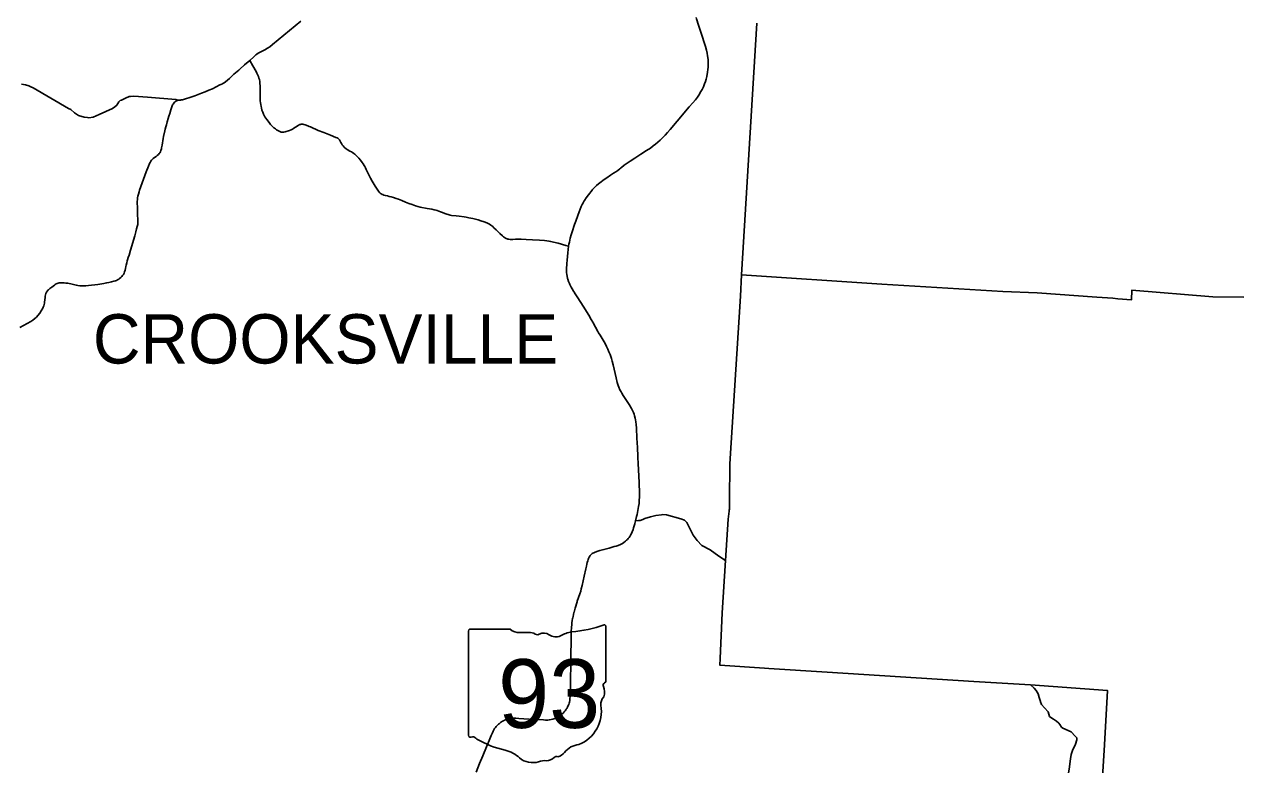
# Model space of a CAD drawing. Extents: x 1761803 to 2441803, y 509895 to 949895.
# Drawn here: x 2058370 to 2107842, y 720477 to 750488 of the extents above; entities that cross this region are included whole.
import ezdxf

# ---------------------------------------------------------------- set-up
doc = ezdxf.new("R2010")
doc.units = 0
for name, color, linetype in [('GM_X_County', 7, 'Continuous'), ('GM_X_County_Road', 7, 'Continuous'), ('GM_X_Minor_Lake', 7, 'Continuous'), ('GM_X_Township_Road', 7, 'Continuous')]:
    doc.layers.add(name, color=color, linetype=linetype)

msp = doc.modelspace()

# ---------------------------------------------------------------- linework, layer by layer
at = {"layer": 'GM_X_County'}
for points in [[(2101907, 716726), (2102194, 721282), (2102313, 723484), (2099188, 723707), (2096896, 723844), (2090939, 724221), (2088582, 724377), (2088401, 724389), (2086592, 724508), (2086607, 724783), (2086686, 726634), (2086822, 728750), (2086931, 730426), (2086970, 730749), (2086973, 730788), (2086976, 730834), (2086979, 730892), (2086981, 730973), (2086981, 731041), (2086978, 731135), (2086980, 731181), (2087001, 732668), (2087421, 739471), (2087469, 740337), (2088090, 750532)], [(2107855, 739434), (2106588, 739441), (2103300, 739712), (2103287, 739317), (2102743, 739362), (2102541, 739394), (2101889, 739433), (2099468, 739598), (2098068, 739659), (2093166, 739956), (2087469, 740337)]]:
    msp.add_lwpolyline(points, dxfattribs=at)
at = {"layer": 'GM_X_Minor_Lake'}
for points in [[(2068067, 749429), (2068070, 749430), (2068133, 749461), (2068231, 749519), (2068325, 749583), (2068440, 749673), (2069593, 750613)], [(2085804, 750213), (2085723, 750464), (2085643, 750717), (2085628, 750763)], [(2085491, 747313), (2085602, 747435), (2085685, 747544), (2085736, 747618), (2085823, 747764), (2085870, 747855), (2085920, 747958), (2085967, 748072), (2086005, 748177), (2086034, 748267), (2086062, 748380), (2086094, 748553), (2086106, 748664), (2086114, 748752), (2086117, 748856), (2086119, 748941), (2086111, 749068), (2086094, 749220), (2086073, 749328), (2086046, 749446), (2086005, 749590), (2085819, 750168), (2085804, 750213)], [(2067067, 748635), (2067106, 748670), (2067308, 748851), (2067512, 749028), (2067675, 749176), (2067714, 749209), (2067763, 749250), (2067806, 749284), (2067857, 749318), (2067904, 749347), (2068067, 749429)], [(2067512, 749028), (2067641, 748808), (2067774, 748574), (2067805, 748511), (2067832, 748456), (2067865, 748377), (2067887, 748314), (2067906, 748248), (2067920, 748176), (2067928, 748097), (2067934, 748004), (2067938, 747642), (2067938, 747517), (2067943, 747395), (2067953, 747302), (2067961, 747236), (2067973, 747159), (2067986, 747106), (2068010, 747017), (2068043, 746929), (2068078, 746848), (2068130, 746746), (2068171, 746680), (2068210, 746626), (2068296, 746516), (2068363, 746434), (2068439, 746354), (2068494, 746299), (2068518, 746278), (2068555, 746248), (2068600, 746219), (2068656, 746187), (2068709, 746158), (2068762, 746136), (2068795, 746125), (2068835, 746119), (2068869, 746119), (2068902, 746124), (2068958, 746138), (2069127, 746192), (2069196, 746218), (2069249, 746243), (2069291, 746268), (2069344, 746304), (2069396, 746340), (2069450, 746375), (2069481, 746395), (2069513, 746413), (2069539, 746426), (2069567, 746436), (2069596, 746441), (2069618, 746444), (2069643, 746444), (2069667, 746441), (2069705, 746433), (2069768, 746414), (2069871, 746377), (2069932, 746353), (2069978, 746331), (2070293, 746190), (2070520, 746100), (2070796, 745993), (2071010, 745909), (2071061, 745887), (2071088, 745872), (2071115, 745852), (2071134, 745832), (2071158, 745804), (2071182, 745757), (2071209, 745704), (2071238, 745658), (2071267, 745612), (2071302, 745565), (2071341, 745517), (2071375, 745483), (2071424, 745441), (2071470, 745411), (2071582, 745350), (2071640, 745319), (2071682, 745292), (2071734, 745257), (2071782, 745222), (2071837, 745173), (2071879, 745131), (2071937, 745067), (2072003, 744988), (2072074, 744891), (2072114, 744832), (2072156, 744769), (2072182, 744725), (2072212, 744673), (2072244, 744612), (2072334, 744419), (2072416, 744256), (2072485, 744136), (2072609, 743931), (2072740, 743723), (2072768, 743686), (2072802, 743650), (2072846, 743617), (2072886, 743596), (2072910, 743585), (2072911, 743585), (2072955, 743569), (2073022, 743550), (2073104, 743532), (2073178, 743513), (2073255, 743493), (2073344, 743467), (2073457, 743432), (2073545, 743402), (2073685, 743352), (2073839, 743287), (2073976, 743230), (2074098, 743180), (2074238, 743130), (2074331, 743104), (2074435, 743081), (2074707, 743029), (2074907, 742993), (2074993, 742975), (2075068, 742957), (2075125, 742941), (2075257, 742893), (2075330, 742863), (2075424, 742826), (2075509, 742796), (2075563, 742776), (2075646, 742755), (2075703, 742744), (2075893, 742722), (2076013, 742710), (2076211, 742685), (2076294, 742673), (2076410, 742648), (2076564, 742615), (2076681, 742589), (2076789, 742560), (2076897, 742524), (2077027, 742478), (2077133, 742439), (2077193, 742413), (2077245, 742385), (2077299, 742350), (2077376, 742288), (2077425, 742245), (2077517, 742161), (2077661, 742017), (2077764, 741911), (2077811, 741871), (2077846, 741846), (2077888, 741822), (2077923, 741805), (2077961, 741791), (2077991, 741782), (2078022, 741776), (2078075, 741769), (2078166, 741770), (2078196, 741772)], [(2064269, 746875), (2064314, 747020), (2064314, 747021), (2064343, 747109), (2064369, 747180), (2064386, 747224), (2064404, 747259), (2064428, 747298), (2064458, 747329), (2064488, 747353), (2064520, 747374), (2064548, 747389), (2064578, 747399), (2064624, 747411), (2064663, 747414), (2064701, 747419), (2064736, 747425), (2064781, 747435), (2064861, 747455), (2064947, 747480), (2065048, 747512), (2065199, 747563), (2065283, 747593), (2065559, 747698), (2065710, 747756), (2065859, 747818), (2066000, 747880), (2066297, 748033), (2066377, 748068), (2066423, 748091), (2066475, 748123), (2066528, 748159), (2066612, 748227), (2066691, 748296), (2066875, 748465), (2067067, 748635)], [(2058247, 748065), (2058411, 748043), (2058549, 748003), (2058634, 747961), (2058725, 747917), (2060163, 747078), (2060248, 747032), (2060406, 746900), (2060572, 746799), (2060792, 746725), (2060926, 746709), (2060979, 746703), (2061161, 746729), (2061403, 746829), (2061945, 747085), (2062045, 747147), (2062121, 747217), (2062207, 747351), (2062253, 747399), (2062305, 747423), (2062471, 747497), (2062619, 747559), (2062673, 747571), (2062810, 747577), (2063362, 747543), (2064514, 747440), (2064560, 747429), (2064624, 747411)], [(2082561, 744655), (2082604, 744688), (2082713, 744775), (2082824, 744856), (2082944, 744945), (2083140, 745069), (2083382, 745224), (2083617, 745375), (2083770, 745476), (2083885, 745562), (2083978, 745636), (2084076, 745716), (2084169, 745799), (2084274, 745899), (2084371, 745998), (2084467, 746105), (2084571, 746225), (2084856, 746562), (2085342, 747144), (2085491, 747313)], [(2058182, 738196), (2058634, 738445), (2058666, 738465), (2058719, 738500), (2058800, 738565), (2058855, 738619), (2058911, 738682), (2058990, 738782), (2059055, 738881), (2059116, 738987), (2059131, 739020), (2059132, 739025), (2059153, 739078), (2059170, 739133), (2059181, 739180), (2059190, 739233), (2059197, 739320), (2059211, 739418), (2059219, 739475), (2059229, 739523), (2059243, 739572), (2059254, 739602), (2059265, 739626), (2059277, 739646), (2059294, 739672), (2059305, 739690), (2059325, 739711), (2059347, 739733), (2059371, 739755), (2059404, 739782), (2059480, 739839), (2059590, 739917), (2059623, 739940), (2059660, 739963), (2059699, 739981), (2059739, 739996), (2059784, 740006), (2059822, 740009), (2059878, 740013), (2059930, 740011), (2059983, 740008), (2060049, 740002), (2060128, 739990), (2060306, 739952), (2060473, 739915), (2060479, 739912), (2060542, 739900), (2060613, 739890), (2060689, 739883), (2060783, 739882), (2060866, 739885), (2060978, 739897), (2061354, 739949), (2061590, 739983), (2061705, 740004), (2061794, 740023), (2061900, 740048), (2061997, 740074), (2062063, 740093), (2062108, 740110), (2062152, 740130), (2062197, 740158), (2062235, 740186), (2062283, 740228), (2062322, 740268), (2062353, 740305), (2062385, 740350), (2062414, 740399), (2062434, 740450), (2062456, 740518), (2062472, 740586), (2062488, 740669), (2062502, 740733), (2062523, 740825), (2062542, 740898), (2062556, 740942), (2062586, 741036), (2062618, 741136), (2062679, 741330), (2062849, 741921), (2062894, 742081), (2062925, 742193), (2062952, 742297), (2062962, 742335), (2062969, 742376), (2062974, 742417), (2062976, 742471), (2062957, 742875), (2062953, 743071), (2062951, 743251), (2062951, 743303), (2062956, 743389), (2062963, 743456), (2062974, 743525), (2062994, 743605), (2063022, 743705), (2063044, 743773), (2063151, 744066), (2063315, 744509), (2063400, 744737), (2063447, 744845), (2063469, 744890), (2063501, 744943), (2063527, 744980), (2063557, 745015), (2063601, 745055), (2063649, 745090), (2063717, 745135), (2063761, 745170), (2063805, 745212), (2063838, 745250), (2063864, 745285), (2063887, 745325), (2063907, 745376), (2063929, 745441), (2063940, 745480), (2063961, 745596), (2064004, 745864), (2064020, 745940), (2064067, 746167), (2064083, 746245), (2064105, 746329), (2064130, 746420), (2064163, 746538), (2064204, 746673), (2064236, 746770), (2064269, 746875)], [(2081422, 743792), (2081435, 743806), (2081494, 743867), (2081589, 743958), (2081661, 744022), (2081719, 744071), (2081891, 744202), (2081998, 744273), (2082154, 744375), (2082274, 744452), (2082372, 744516), (2082447, 744571), (2082530, 744632), (2082561, 744655)], [(2081085, 743329), (2081098, 743352), (2081161, 743451), (2081253, 743581), (2081403, 743770), (2081422, 743792)], [(2080451, 741497), (2080467, 741578), (2080482, 741659), (2080518, 741817), (2080558, 741960), (2080596, 742081), (2080694, 742369), (2080745, 742513), (2080823, 742745), (2080878, 742893), (2080921, 743000), (2080966, 743105), (2081004, 743180), (2081042, 743251), (2081085, 743329)], [(2078196, 741772), (2078295, 741779), (2078381, 741781), (2078457, 741782), (2078531, 741780), (2078736, 741770), (2078985, 741754), (2079268, 741737), (2079469, 741722), (2079566, 741713), (2079651, 741703), (2079723, 741689), (2080029, 741613), (2080337, 741528), (2080451, 741497)], [(2081444, 738393), (2081429, 738420), (2081369, 738530), (2081274, 738694), (2081040, 739066), (2080947, 739211), (2080804, 739437), (2080694, 739611), (2080695, 739614), (2080653, 739676), (2080599, 739766), (2080557, 739837), (2080505, 739940), (2080486, 739980), (2080454, 740059), (2080425, 740154), (2080414, 740190), (2080394, 740282), (2080381, 740352), (2080373, 740435), (2080370, 740517), (2080370, 740580), (2080372, 740641), (2080376, 740710), (2080381, 740797), (2080393, 740933), (2080416, 741224), (2080451, 741497)], [(2081671, 737980), (2081632, 738042), (2081444, 738393)], [(2083263, 732971), (2083246, 733332), (2083226, 733707), (2083204, 734122), (2083193, 734261), (2083182, 734381), (2083169, 734462), (2083155, 734529), (2083131, 734620), (2083109, 734685), (2083083, 734752), (2083042, 734840), (2083000, 734918), (2082907, 735072), (2082805, 735233), (2082724, 735359), (2082671, 735442), (2082613, 735538), (2082581, 735594), (2082536, 735677), (2082488, 735779), (2082459, 735854), (2082422, 735963), (2082377, 736154), (2082301, 736516), (2082264, 736681), (2082224, 736832), (2082191, 736936), (2082175, 736985), (2082133, 737102), (2082090, 737214), (2082042, 737322), (2081989, 737435), (2081932, 737546), (2081858, 737679), (2081727, 737891), (2081671, 737980)], [(2083141, 730257), (2083167, 730358), (2083214, 730533), (2083235, 730619), (2083268, 730774), (2083295, 730939), (2083311, 731067), (2083321, 731166), (2083331, 731344), (2083332, 731465), (2083316, 731917), (2083277, 732680), (2083265, 732924), (2083263, 732971)], [(2082490, 729375), (2082528, 729391), (2082590, 729420), (2082638, 729448), (2082695, 729484), (2082763, 729538), (2082808, 729577), (2082839, 729607), (2082872, 729645), (2082906, 729686), (2082938, 729730), (2082970, 729781), (2083002, 729842), (2083037, 729919), (2083069, 730008), (2083089, 730075), (2083137, 730240), (2083141, 730257)], [(2083167, 730358), (2083289, 730369), (2083355, 730374), (2083470, 730421)], [(2083470, 730421), (2083541, 730451), (2083781, 730521), (2083995, 730578), (2084221, 730609), (2084279, 730613)], [(2084279, 730613), (2084421, 730598), (2085005, 730437), (2085153, 730383), (2085244, 730293), (2085421, 729936), (2085508, 729780), (2085667, 729562), (2085861, 729356), (2086194, 729186), (2086554, 728928), (2086822, 728750)], [(2081682, 729143), (2081718, 729154), (2081886, 729198), (2082100, 729256), (2082305, 729315), (2082385, 729339), (2082423, 729350), (2082461, 729363), (2082490, 729375)], [(2081086, 728118), (2081086, 728119), (2081150, 728409), (2081177, 728523), (2081194, 728599), (2081210, 728668), (2081227, 728734), (2081242, 728787), (2081259, 728835), (2081272, 728862), (2081285, 728887), (2081308, 728925), (2081326, 728949), (2081349, 728976), (2081383, 729009), (2081410, 729030), (2081438, 729048), (2081470, 729067), (2081501, 729082), (2081532, 729096), (2081566, 729108), (2081597, 729118), (2081682, 729143)], [(2080805, 727098), (2080905, 727395), (2080942, 727506), (2080967, 727604), (2080997, 727733), (2081086, 728118)], [(2080668, 726641), (2080673, 726664), (2080699, 726762), (2080717, 726825), (2080797, 727073), (2080805, 727098)], [(2080568, 726018), (2080572, 726065), (2080579, 726136), (2080590, 726227), (2080603, 726320), (2080617, 726399), (2080623, 726434), (2080631, 726478), (2080649, 726563), (2080668, 726641)], [(2080524, 723554), (2080525, 723594), (2080530, 724021), (2080538, 724421), (2080545, 724864), (2080544, 724912), (2080554, 725497), (2080555, 725746), (2080556, 725762)], [(2080556, 725762), (2080562, 725912), (2080566, 725993), (2080568, 726018)], [(2077199, 721392), (2077308, 721655), (2077335, 721717), (2077360, 721771), (2077390, 721835), (2077416, 721883), (2077449, 721938), (2077484, 721985), (2077515, 722023), (2077581, 722092), (2077601, 722111), (2077630, 722136), (2077656, 722157), (2077687, 722179), (2077726, 722205), (2077769, 722232), (2077807, 722252), (2077847, 722272), (2077894, 722291), (2077940, 722308), (2077990, 722323), (2078044, 722337), (2078091, 722344), (2078160, 722351), (2078218, 722355), (2078305, 722354), (2078429, 722348), (2079059, 722310), (2079439, 722287), (2079511, 722284), (2079558, 722283), (2079604, 722285), (2079668, 722290), (2079739, 722302), (2079809, 722318), (2079894, 722346), (2079967, 722377), (2080061, 722428), (2080125, 722472), (2080178, 722516), (2080225, 722557), (2080277, 722613), (2080318, 722663), (2080342, 722696), (2080358, 722719), (2080380, 722758), (2080407, 722806), (2080436, 722867), (2080456, 722918), (2080471, 722962), (2080484, 723014), (2080498, 723078), (2080508, 723157), (2080514, 723233), (2080517, 723311), (2080524, 723554)], [(2099603, 723024), (2099597, 723039), (2099546, 723193), (2099502, 723343), (2099424, 723487), (2099342, 723582), (2099188, 723707)], [(2101080, 721504), (2101076, 721557), (2101009, 721626), (2100843, 721799), (2100508, 721954), (2100457, 722001), (2100391, 722104), (2100347, 722153), (2100254, 722238), (2100121, 722318), (2100058, 722355), (2099967, 722433), (2099908, 722617), (2099760, 722780), (2099644, 722919), (2099603, 723024)], [(2076695, 720176), (2076839, 720520), (2076967, 720829), (2077121, 721200), (2077189, 721366), (2077199, 721392)], [(2100572, 716815), (2100571, 716851), (2100568, 716979), (2100564, 717050), (2100492, 717189), (2100433, 717306), (2100418, 717362), (2100421, 717417), (2100438, 717470), (2100450, 717524), (2100481, 717839), (2100512, 718284), (2100512, 718462), (2100543, 718875), (2100669, 719702), (2100686, 719812), (2100760, 720292), (2100818, 720708), (2100851, 720884), (2100904, 721052), (2101021, 721309), (2101081, 721479), (2101080, 721504)]]:
    msp.add_lwpolyline(points, dxfattribs=at)
at = {"layer": 'GM_X_Township_Road'}
for p, q in [((2076391, 725893), (2076391, 721667)), ((2078076, 725966), (2076446, 725966)), ((2081959, 723860), (2081959, 726071)), ((2081959, 723860), (2081959, 723860))]:
    msp.add_line(p, q, dxfattribs=at)
for centre, radius, start, end in [((2076455, 725902), 64.5, 98.1301, 188.1301), ((2078465, 726457), 626, 231.6195, 271.1119), ((2078672, 723593), 2246, 80.4867, 94.9883), ((2079182, 725924), 181, 219.7921, 297.1024), ((2079447, 725436), 375, 54.4667, 119.1411), ((2080729, 724675), 1188, 97.3462, 120.7689), ((2079976, 731728), 5905, 275.8445, 288.9065), ((2081898, 726080), 62, 351.8621, 97.738), ((2079932, 726106), 452, 233.8562, 294.8282), ((2081945, 723697), 95.9, 107.944, 210.337), ((2081893, 723851), 66.3, 289.6038, 7.7341), ((2081335, 723418), 576, 340.033, 23.6496), ((2080307, 722653), 1477, 292.3089, 8.9858), ((2082181, 722934), 419, 136.8065, 186.9296), ((2076455, 721657), 65.1, 171.9584, 258.3066), ((2076465, 722090), 497, 267.339, 280.6039), ((2076567, 721423), 179, 29.7484, 93.2717), ((2078828, 725220), 4265, 240.4129, 257.1985), ((2077556, 719768), 1334, 47.1842, 75.836), ((2079904, 721257), 477, 282.8732, 323.2771), ((2080929, 720480), 809, 94.4031, 142.5768), ((2078999, 721402), 847, 230.7004, 286.2918), ((2079489, 719941), 696, 85.6951, 111.2099), ((2079550, 721085), 451, 268.777, 315.5493), ((2079959, 720676), 127, 65.7517, 132.6484)]:
    msp.add_arc(centre, radius, start, end, dxfattribs=at)

# ---------------------------------------------------------------- texts
at = {"layer": 'GM_X_County_Road'}
msp.add_text('CROOKSVILLE', height=2000, rotation=0, dxfattribs=at).set_placement((2061149, 736739))
at = {"layer": 'GM_X_Township_Road'}
msp.add_text('93', height=2784.4, dxfattribs=at).set_placement((2077592, 721965))

doc.saveas('drawing.dxf')
